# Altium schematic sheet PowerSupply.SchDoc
size A
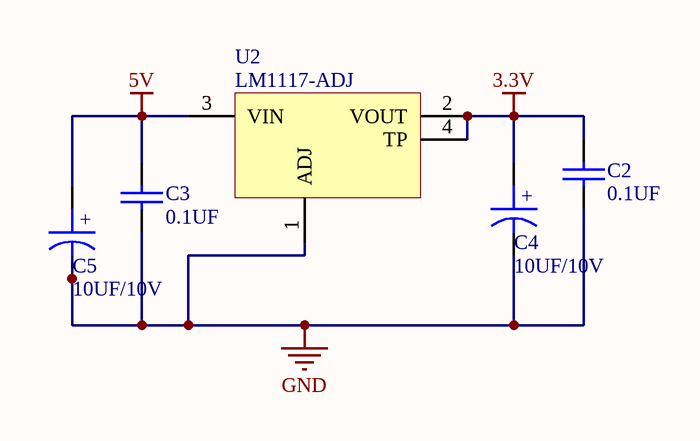
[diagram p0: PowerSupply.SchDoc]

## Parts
C2  0.1UF  [CAPC0603]
C3  0.1UF  [CAPC0603]
C4  10UF/10V  [CAPC1206_TANTALUM]
C5  10UF/10V  [CAPC1206_TANTALUM]
U2  LM1117-ADJ  [SOT223]

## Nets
3.3V: C2.1 C4.1 U2.2(VOUT) U2.4(TP)
5V: C3.1 C5.1 U2.3(VIN)
GND: C2.2 C3.2 C4.2 C5.2 U2.1(ADJ)

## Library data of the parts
C2 C3 = CAP NP
C4 C5 = CAP
U2 = LM1117-3.3V_ADJ: 3.3V LDO REGULATOR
